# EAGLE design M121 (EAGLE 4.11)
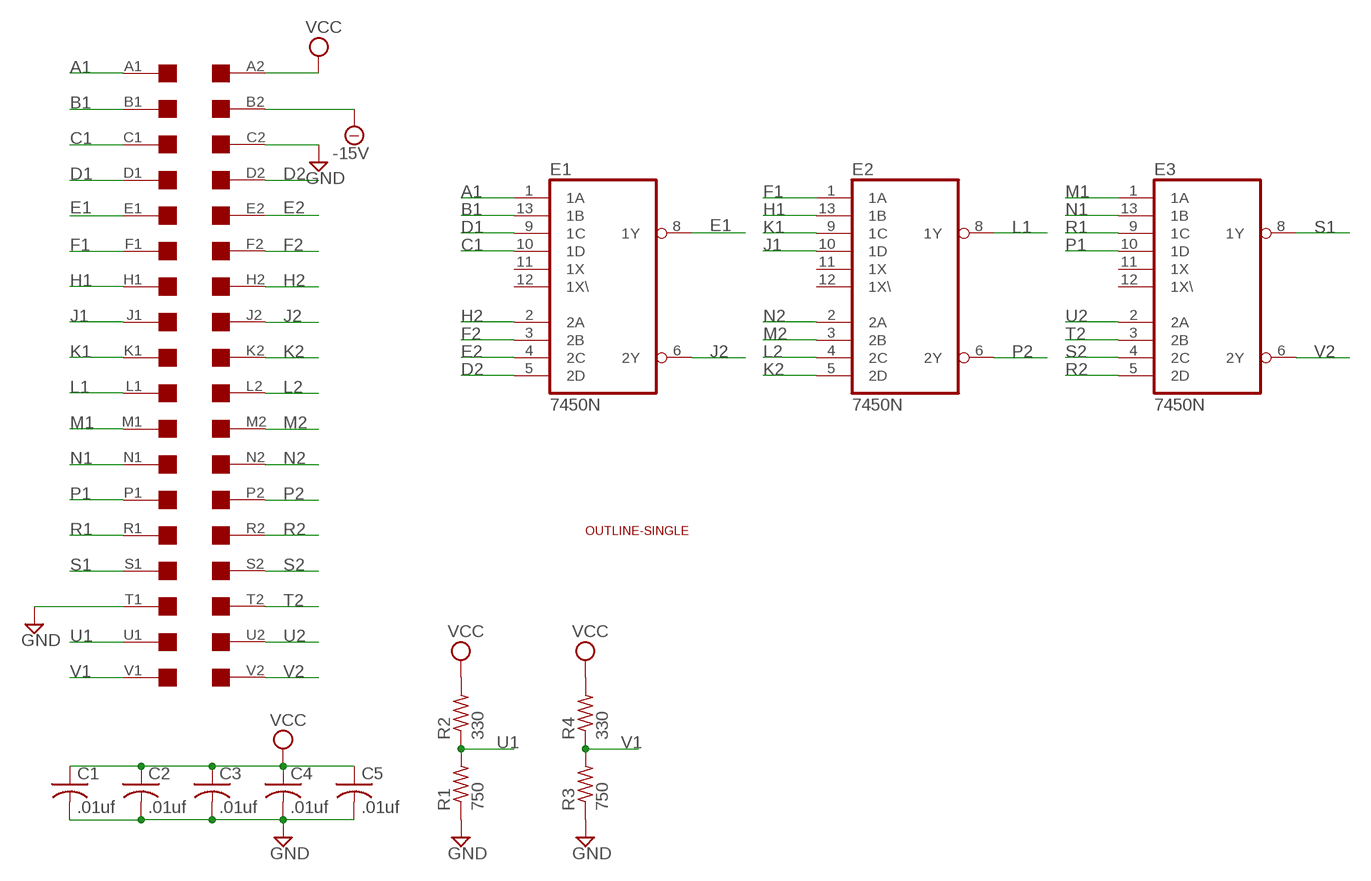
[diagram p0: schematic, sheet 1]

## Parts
C1  .01uf  C-US050-025X075  [C050-025X075]
C2  .01uf  C-US050-025X075  [C050-025X075]
C3  .01uf  C-US050-025X075  [C050-025X075]
C4  .01uf  C-US050-025X075  [C050-025X075]
C5  .01uf  C-US050-025X075  [C050-025X075]
E1  7450N  [DIL14]
E2  7450N  [DIL14]
E3  7450N  [DIL14]
R1  750  R-US_0207/10  [0207/10]
R2  330  R-US_0207/10  [0207/10]
R3  750  R-US_0207/10  [0207/10]
R4  330  R-US_0207/10  [0207/10]
U$1  OUTLINE-SINGLE  [SINGLE]
U$4  SINGLE  [EDGE-CON2]

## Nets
-15V: U$4.B2
A1: E1.1(1A) U$4.A1
B1: E1.13(1B) U$4.B1
C1: E1.10(1D) U$4.C1
D1: E1.9(1C) U$4.D1
D2: E1.5(2D) U$4.D2
E1: E1.8(1Y) U$4.E1
E2: E1.4(2C) U$4.E2
F1: E2.1(1A) U$4.F1
F2: E1.3(2B) U$4.F2
GND: C1.2 C2.2 C3.2 C4.2 C5.2 R1.1 R3.1 U$4.C2 U$4.T1
H1: E2.13(1B) U$4.H1
H2: E1.2(2A) U$4.H2
J1: E2.10(1D) U$4.J1
J2: E1.6(2Y) U$4.J2
K1: E2.9(1C) U$4.K1
K2: E2.5(2D) U$4.K2
L1: E2.8(1Y) U$4.L1
L2: E2.4(2C) U$4.L2
M1: E3.1(1A) U$4.M1
M2: E2.3(2B) U$4.M2
N1: E3.13(1B) U$4.N1
N2: E2.2(2A) U$4.N2
P1: E3.10(1D) U$4.P1
P2: E2.6(2Y) U$4.P2
R1: E3.9(1C) U$4.R1
R2: E3.5(2D) U$4.R2
S1: E3.8(1Y) U$4.S1
S2: E3.4(2C) U$4.S2
T2: E3.3(2B) U$4.T2
U1: R1.2 R2.1 U$4.U1
U2: E3.2(2A) U$4.U2
V1: R3.2 R4.1 U$4.V1
V2: E3.6(2Y) U$4.V2
VCC: C1.1 C2.1 C3.1 C4.1 C5.1 R2.2 R4.2 U$4.A2
Unconnected: E1.11(1X) E1.12(1X\) E2.11(1X) E2.12(1X\) E3.11(1X) E3.12(1X\)

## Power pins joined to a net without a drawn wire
GND: E1.7(GND) E2.7(GND) E3.7(GND)
VCC: E1.14(VCC) E2.14(VCC) E3.14(VCC)

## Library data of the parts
C1-C5 = rcl:C-US: CAPACITOR, American symbol
E1-E3 = 74xx-us:74*50: Dual 2-wide 2-input AND OR INVERTER gate (one gate expandable)
R1-R4 = rcl:R-US_: RESISTOR, American symbol
U$1 = dec-con:OUTLINE-*: Board outlines for DEC boards.
U$4 = dec-con:SINGLE: Single-Height DEC board

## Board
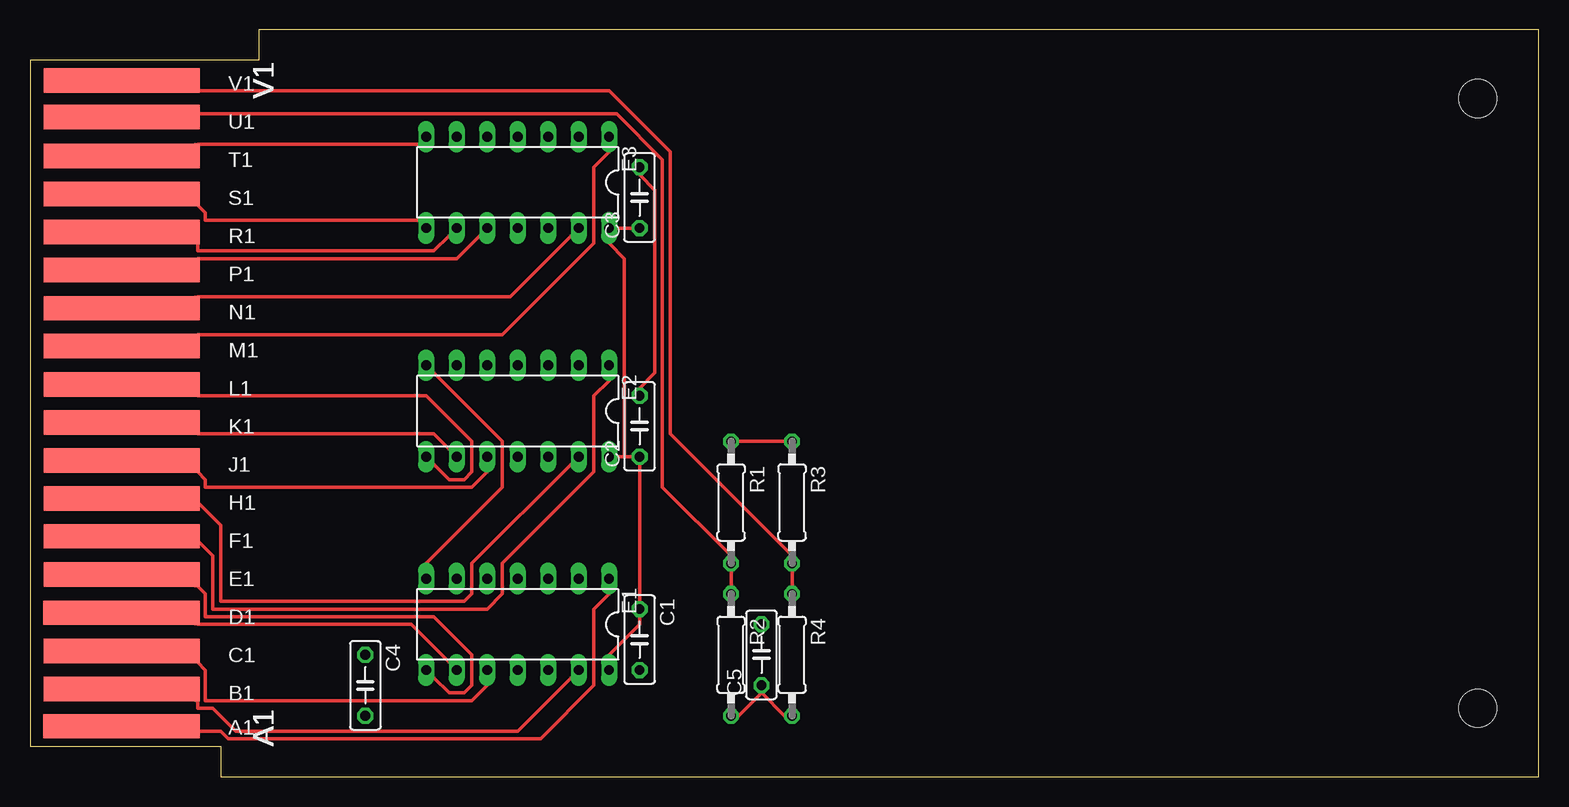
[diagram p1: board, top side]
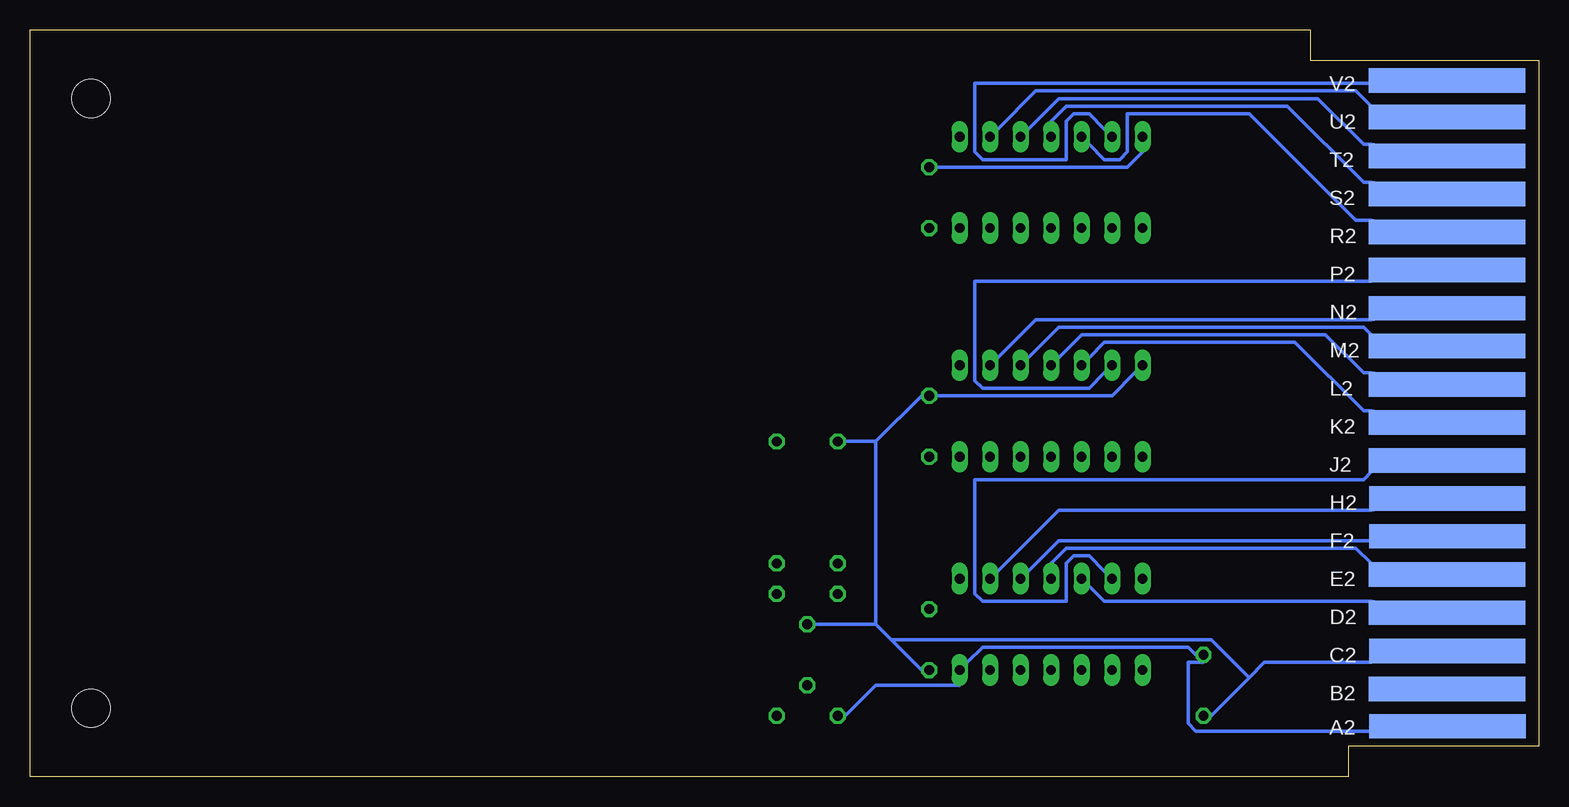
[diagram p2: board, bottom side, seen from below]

Size 125.73 x 62.23 mm. Coordinates in mm from the lower left corner, seen from the top.
Copper layers (1*16): Top 0.035mm / dielectric 1.5mm / Bottom 0.035mm
Design rules "10mils": minimum track width 12mil, minimum drill 28mil, track to track 10mil, track to pad 10mil, pad to pad 10mil, via to via 10mil, smd to smd 10mil, copper to edge 25mil, drill to drill 10mil, minimum pad ring 10mil, minimum via ring 8mil, stop-mask expansion 0mil, vias tented up to drill 0mil, thermal gap 10mil

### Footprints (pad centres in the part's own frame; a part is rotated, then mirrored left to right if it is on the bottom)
C050-025X075 = drill 0.813 octagon: 1 -2.54,0; 2 2.54,0
DIL14 = drill 0.813 long: 1 -7.62,-3.81; 2 -5.08,-3.81; 3 -2.54,-3.81; 4 0,-3.81; 5 2.54,-3.81; 6 5.08,-3.81; 7 7.62,-3.81; 8 7.62,3.81; 9 5.08,3.81; 10 2.54,3.81; 11 0,3.81; 12 -2.54,3.81; 13 -5.08,3.81; 14 -7.62,3.81
0207/10 = drill 0.813 octagon: 1 -5.08,0; 2 5.08,0
SINGLE = hole 3.175: 120.65,56.515; 120.65,5.715
EDGE-CON2 = smd 13.017 x 2.032: A1 7.633,4.207; B1 7.639,7.327; C1 7.636,10.489; D1 7.633,13.665; E1 7.642,16.84; F1 7.642,20.041; H1 7.642,23.19; J1 7.642,26.34; K1 7.642,29.515; L1 7.642,32.69; M1 7.642,35.89; N1 7.642,39.04; P1 7.642,42.24; R1 7.642,45.39; S1 7.642,48.565; T1 7.642,51.74; U1 7.642,54.966; V1 7.642,58.026 | smd 13.017 x 2.032 bottom: A2 7.614,4.207; B2 7.642,7.328; C2 7.617,10.49; D2 7.642,13.665; E2 7.642,16.84; F2 7.617,20.041; H2 7.617,23.19; J2 7.642,26.34; K2 7.642,29.515; L2 7.642,32.69; M2 7.642,35.89; N2 7.642,39.04; P2 7.642,42.24; R2 7.642,45.39; S2 7.642,48.565; T2 7.642,51.74; U2 7.642,54.966; V2 7.642,58.026

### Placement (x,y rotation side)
C1  50.8,11.43 270 top
C2  50.8,29.21 90 top
C3  50.8,48.26 90 top
C4  27.94,7.62 270 top
C5  60.96,10.16 90 top
E1  40.64,12.7 180 top
E2  40.64,30.48 180 top
E3  40.64,49.53 180 top
R1  58.42,22.86 270 top
R2  58.42,10.16 270 top
R3  63.5,22.86 270 top
R4  63.5,10.16 270 top
U$1  0,0 0 top
U$4  0,0 0 top

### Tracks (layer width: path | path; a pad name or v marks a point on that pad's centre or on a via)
A1
  Top 0.305: E1.1 48.26,15.24 46.99,13.97 46.99,7.62 42.55,3.17 16.51,3.17 15.88,3.81 13.97,3.81 U$4.A1
B1
  Top 0.305: E1.13 45.09,8.26 40.64,3.81 17.15,3.81 15.24,5.71 13.97,5.71 13.97,6.35 U$4.B1
C1
  Top 0.305: E1.10 38.1,7.62 36.83,6.35 14.61,6.35 14.61,8.89 13.97,9.53 U$4.C1
D1
  Top 0.305: E1.9 34.93,9.53 31.75,12.7 13.97,12.7 U$4.D1
D2
  Bottom 0.305: E1.5 37.47,15.88 36.2,14.61 13.97,14.61 U$4.D2
E1
  Top 0.305: E1.8 33.66,8.26 34.93,6.99 36.2,6.99 36.83,7.62 36.83,10.16 33.66,13.34 14.61,13.34 14.61,15.24 13.97,15.88 U$4.E1
E2
  Bottom 0.305: E1.4 40.64,17.78 39.37,19.05 15.24,19.05 13.97,17.78 U$4.E2
F1
  Top 0.305: E2.1 48.26,33.02 46.99,31.75 46.99,25.4 39.37,17.78 39.37,15.24 38.1,13.97 15.24,13.97 15.24,18.41 13.97,19.68 U$4.F1
F2
  Bottom 0.305: E1.3 42.55,17.14 40.01,19.68 13.97,19.68 U$4.F2
GND
  Top 0.305: E3.7 32.39,52.7 13.97,52.7 U$4.T1 | E1.7 33.02,17.78 39.37,24.13 39.37,27.94 33.66,33.66 E2.7 | R1.1 59.06,27.94 62.87,27.94 R3.1 | C3.2 50.8,50.16 52.07,48.9 52.07,33.66 50.8,32.38 C2.2
  Bottom 0.305: C3.2 50.17,50.8 34.29,50.8 33.02,52.07 E3.7 | 24.13,8.26 22.86,9.53 13.97,9.53 U$4.C2 | 24.13,8.26 27.31,5.08 C4.2 | 53.98,11.43 55.25,12.7 | 53.98,11.43 51.44,8.89 C1.2 | 55.25,12.7 60.33,12.7 C5.2 | 55.25,27.94 51.44,31.75 C2.2 50.17,31.75 35.56,31.75 33.66,33.66 E2.7 | 55.25,27.94 57.79,27.94 R1.1 | 55.25,12.7 55.25,27.94 | 24.13,8.26 27.31,11.43 53.98,11.43
H1
  Top 0.305: E2.13 45.09,26.04 36.83,17.78 36.83,15.24 36.2,14.61 15.88,14.61 15.88,20.95 13.97,22.86 U$4.H1
H2
  Bottom 0.305: E1.2 45.09,17.14 40.01,22.23 13.97,22.23 U$4.H2
J1
  Top 0.305: E2.10 38.1,25.4 36.83,24.13 14.61,24.13 14.61,24.77 13.97,25.4 U$4.J1
J2
  Bottom 0.305: E1.6 36.2,17.14 37.47,18.41 38.74,18.41 39.37,17.78 39.37,14.61 46.36,14.61 46.99,15.24 46.99,24.77 14.61,24.77 13.97,25.4 U$4.J2
K1
  Top 0.305: E2.9 34.93,27.3 33.66,28.57 13.97,28.57 U$4.K1
K2
  Bottom 0.305: E2.5 37.47,34.92 36.2,36.2 20.32,36.2 14.61,30.48 13.97,30.48 U$4.K2
L1
  Top 0.305: E2.8 33.66,26.04 34.93,24.77 36.2,24.77 36.83,25.4 36.83,27.94 33.02,31.75 13.97,31.75 U$4.L1
L2
  Bottom 0.305: E2.4 40.01,34.92 38.1,36.83 17.78,36.83 14.61,33.66 13.97,33.66 U$4.L2
M1
  Top 0.305: E3.1 48.26,52.07 46.99,50.8 46.99,44.45 39.37,36.83 13.97,36.83 U$4.M1
M2
  Bottom 0.305: E2.3 42.55,34.92 40.01,37.47 14.61,37.47 13.97,36.83 U$4.M2
N1
  Top 0.305: E3.13 45.09,45.09 40.01,40.01 13.97,40.01 U$4.N1
N2
  Bottom 0.305: E2.2 45.09,34.92 41.91,38.1 13.97,38.1 U$4.N2
P1
  Top 0.305: E3.10 37.47,45.09 35.56,43.18 13.97,43.18 U$4.P1
P2
  Bottom 0.305: E2.6 36.2,33.66 37.47,32.38 46.36,32.38 46.99,33.02 46.99,41.27 13.97,41.27 U$4.P2
R1
  Top 0.305: E3.9 34.93,45.09 33.66,43.81 13.97,43.81 13.97,44.45 U$4.R1
R2
  Bottom 0.305: E3.5 37.47,52.7 36.2,51.44 34.93,51.44 34.29,52.07 34.29,55.24 24.13,55.24 15.24,46.35 13.97,46.35 U$4.R2
S1
  Top 0.305: E3.8 32.39,46.35 14.61,46.35 14.61,46.99 13.97,47.62 U$4.S1
S2
  Bottom 0.305: E3.4 40.64,54.61 39.37,55.88 20.96,55.88 14.61,49.53 13.97,49.53 U$4.S2
T2
  Bottom 0.305: E3.3 42.55,53.98 40.01,56.52 18.42,56.52 14.61,52.7 13.97,52.7 U$4.T2
U1
  Top 0.305: R2.1 58.42,15.88 58.42,17.14 R1.2 58.42,18.41 52.71,24.13 52.71,51.44 48.9,55.24 13.97,55.24 U$4.U1
U2
  Bottom 0.305: E3.2 45.09,53.98 41.91,57.15 15.24,57.15 13.97,55.88 U$4.U2
V1
  Top 0.305: R4.1 63.5,15.88 63.5,17.14 R3.2 63.5,18.41 53.34,28.57 53.34,52.07 48.26,57.15 13.97,57.15 U$4.V1
V2
  Bottom 0.305: E3.6 36.2,53.98 37.47,55.24 38.74,55.24 39.37,54.61 39.37,51.44 46.36,51.44 46.99,52.07 46.99,57.78 13.97,57.78 U$4.V2
VCC
  Top 0.305: 60.96,6.99 59.06,5.08 R2.2 | 60.96,6.99 C5.1 60.96,6.99 | 60.96,6.99 62.87,5.08 R4.2 | C3.1 50.17,45.72 48.9,45.72 E3.14 48.26,44.45 49.53,43.18 49.53,26.67 | 49.53,26.67 50.17,26.67 C2.1 50.8,26.04 50.8,14.61 C1.1 50.8,13.34 50.8,12.7 48.26,10.16 E1.14 | 49.53,26.67 48.9,26.67 E2.14
  Bottom 0.305: R2.2 57.79,5.08 55.25,7.62 48.26,7.62 E1.14 47.63,9.53 46.36,10.79 29.21,10.79 28.58,10.16 C4.1 27.94,9.53 29.21,9.53 29.21,4.45 28.58,3.81 13.97,3.81 U$4.A2

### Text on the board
tNames: V1 | V1 | V1 | V1 | V1 | V1 | V1 | V1 | V1 | V1 | V1 | V1 | V1 | V1 | V1 | V1 | V1 | V1 | V1 | V1 | V1 | V1 | V1 | V1 | V1 | V1 | V1 | V1 | V1 | V1 | V1 | V1 | A1 | A1 | A1 | A1 | A1 | A1 | A1 | A1 | A1 | A1 | A1 | A1 | A1 | A1 | A1 | A1 | A1 | A1 | A1 | A1 | A1 | A1 | A1 | A1 | A1 | A1 | A1 | A1 | A1 | A1 | A1 | A1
